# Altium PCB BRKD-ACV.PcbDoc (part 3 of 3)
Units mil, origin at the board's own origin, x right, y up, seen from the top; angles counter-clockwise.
Board outline 5708.66 x 3740.16 mil, 4 copper layers (L1-TOP, L2-GND, L3-PWR, L4-BOT), stack 61.722 mil thick; 171 components, 263 nets, 918 pads, 406 vias.
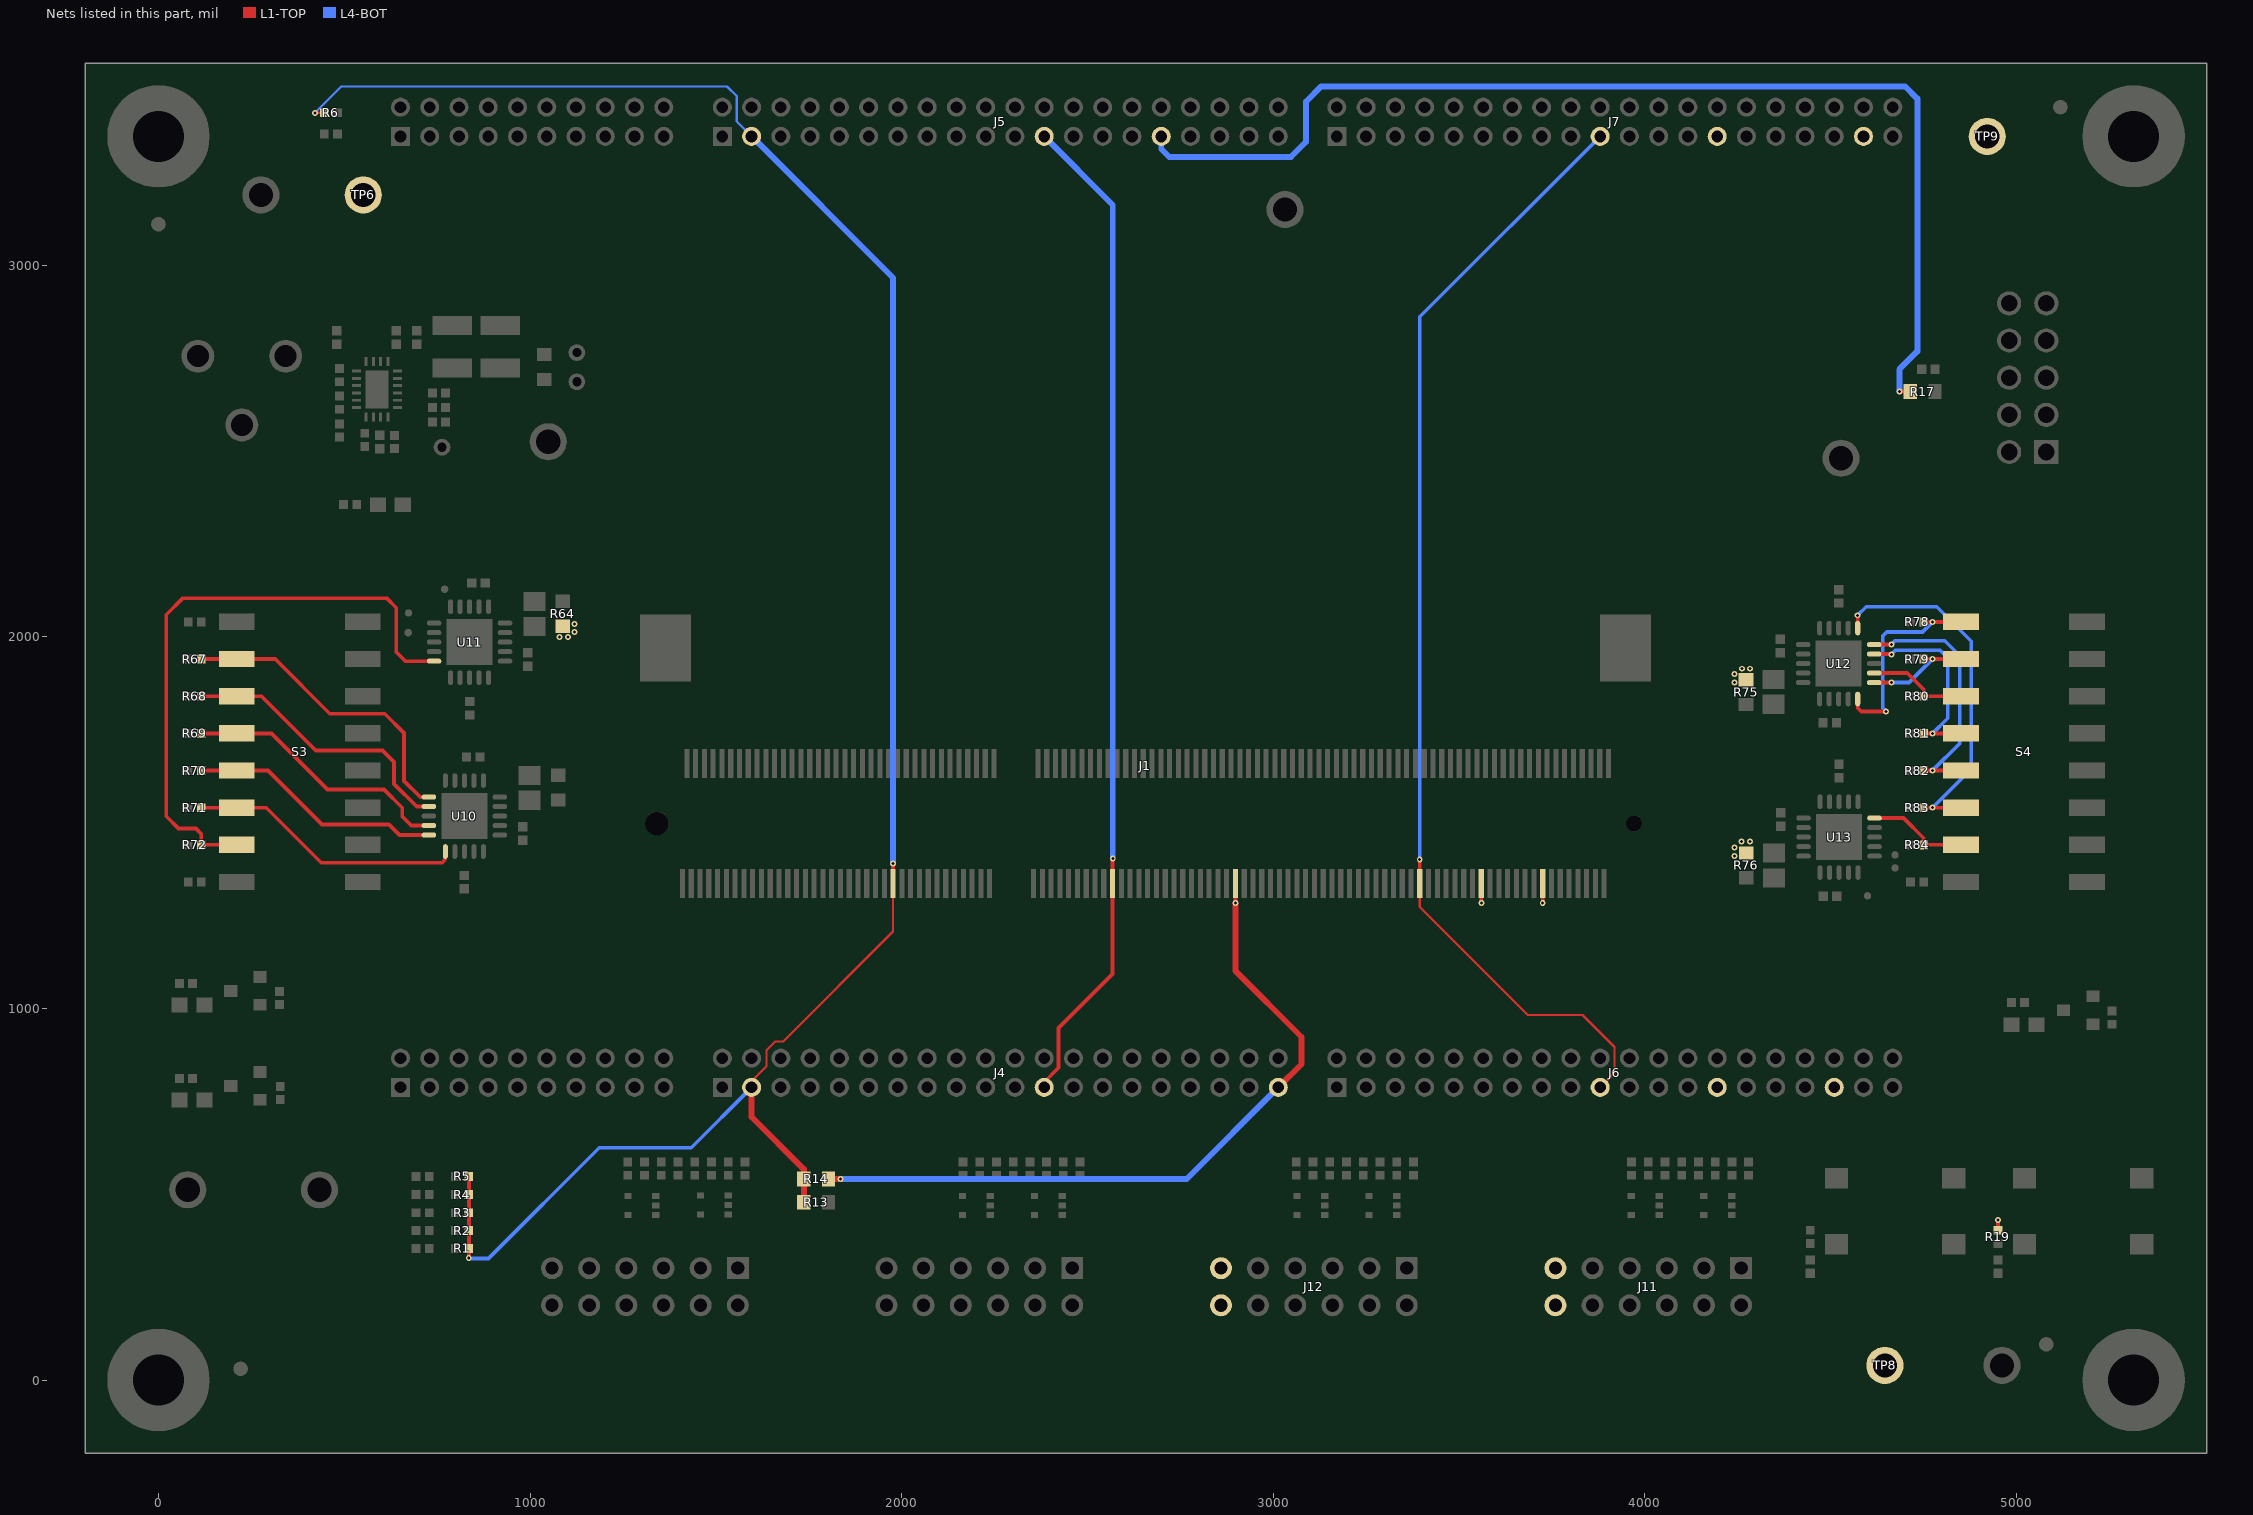
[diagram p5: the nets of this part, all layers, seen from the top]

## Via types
v1: diameter 16, hole 8, L1-TOP to L4-BOT, tented both sides, 406 vias

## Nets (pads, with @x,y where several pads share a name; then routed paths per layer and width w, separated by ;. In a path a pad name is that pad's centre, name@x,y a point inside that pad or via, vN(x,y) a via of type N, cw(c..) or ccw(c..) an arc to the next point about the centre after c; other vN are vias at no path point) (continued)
VCCIO1_100MV: R67.2 S3.2 U10.6 | length 841.6
  L1-TOP w10: R67.2@115.43,1940 S3.2@210.5,1940 314,1940 461,1793 609,1793 661,1741 661,1612 704.24,1568.76 U10.6@727.71,1568.76
VCCIO1_200MV: R68.2 S3.3 U10.7 | length 769.8
  L1-TOP w10: R68.2@115.43,1840 S3.3@210.5,1840 277,1840 423,1694 603,1694 634,1663 634,1604 694.83,1543.17 U10.7@727.71,1543.17
VCCIO1_400MV: R69.2 S3.4 U10.9 | length 729.1
  L1-TOP w10: R69.2@115.43,1740 S3.4@210.5,1740 304,1740 455,1589 607,1589 656,1540 656,1516 680.02,1491.98 U10.9@727.71,1491.98
VCCIO1_800MV: R70.2 S3.5 U10.10 | length 684.2
  L1-TOP w10: R70.2@115.43,1640 S3.5@210.5,1640 295,1640 440,1495 620,1495 648.61,1466.39 U10.10@727.71,1466.39
VCCIO1_1600MV: R71.2 S3.6 U10.11 | length 742.7
  L1-TOP w10: R71.2@115.43,1540 S3.6@210.5,1540 290,1540 438,1392 763,1392 772,1401 U10.11@772,1422.1
VCCIO2: J1.175 J6.27 J7.27 J11.6 J11.12 J12.6 J12.12 R19.2 R75.2 TP8.1 | length 79.4
  L1-TOP w10: J1.175@3559.56,1335.92 3559.56,1284.44 v1(3560,1284) ; R19.2@4950,402.72 v1(4950,430)
  other v1: 4241,1877 4241,1900 4261,1914 4283,1914
VCCIO2_50MV: R78.2 S4.1 U12.5 | length 561.3
  L1-TOP w10: U12.5@4572.54,1832.39 4572.54,1808.46 4582,1799 v1(4649,1799) ; R78.2@4750,2040 v1(4774,2040) S4.1@4850.5,2040
  L4-BOT w10: v1(4649,1799) 4640,1808 4640,2002 4651,2013 4747,2013 v1(4774,2040)
VCCIO2_100MV: R79.2 S4.2 U12.6 | length 284
  L1-TOP w10: U12.6@4616.83,1876.69 4662.68,1876.69 v1(4663,1877) ; R79.2@4750,1940 v1(4774,1940) S4.2@4850.5,1940
  L4-BOT w10: v1(4663,1877) 4710.73,1877 4710.87,1876.87 v1(4774,1940)
VCCIO2_200MV: R80.2 S4.3 U12.7 | length 270
  L1-TOP w10: U12.7@4616.83,1902.28 4705.72,1902.28 4750,1858 R80.2@4750,1840 S4.3@4850.5,1840
VCCIO2_400MV: R81.2 S4.4 U12.9 | length 532
  L1-TOP w10: U12.9@4616.83,1953.46 v1@4663,1953.46 ; R81.2@4750,1740 v1(4774,1740) S4.4@4850.5,1740
  L4-BOT w10: v1(4663,1952.87) 4674.13,1964 4794,1964 4815,1943 4815,1781 v1(4774,1740)
VCCIO2_800MV: R82.2 S4.5 U12.10 | length 690.7
  L1-TOP w10: U12.10@4616.83,1979.05 v1@4663,1979.05 ; R82.2@4750,1640 v1(4774,1640) S4.5@4850.5,1640
  L4-BOT w10: v1(4663,1978.87) 4673.13,1989 4807,1989 4847,1949 4847,1713 v1(4774,1640)
VCCIO2_1600MV: R83.2 S4.6 U12.11 | length 979.9
  L1-TOP w10: v1(4572.36,2057.87) 4572.54,2057.69 U12.11@4572.54,2023.34 ; R83.2@4750,1540 v1(4774,1540) S4.6@4850.5,1540
  L4-BOT w10: v1(4572.36,2057.87) 4595.5,2081 4785,2081 4878,1988 4878,1644 v1(4774,1540)
VCCPD1: J1.119 J4.39 J5.31 R14.1 R17.2 R64.2 TP6.1 | length 5030.9
  L1-TOP w10: v1(2898,1284) 2898.14,1284.14 J1.119@2898.14,1335.92 ; v1(4684.54,2660) R17.2@4714.07,2660
  L1-TOP w16: R14.1@1803.46,541 v1(1835,541) ; v1(2898,1284) 2898,1101 3076,923 3076,850.02 J4.39@3013.39,787.4
  L4-BOT w16: v1(1835,541) 2766.98,541 J4.39@3013.39,787.4 ; J5.31@2698.43,3346.46 2698.43,3312.57 2720,3291 3047,3291 3088,3332 3088,3440 3129,3481 4700,3481 4733,3448 4733,2768 4684.54,2719.54 v1(4684.54,2660)
  other v1: 1079,1999 1102,1999 1120,2013 1120,2034
VCCPD1_25B_33: R72.2 S3.7 U11.10 | length 1660
  L1-TOP w10: S3.7@210.5,1440 R72.2@115.43,1440 115.43,1469.57 101,1484 54,1484 21,1517 21,2059 66,2104 614,2104 640,2078 640,1959 664.61,1934.39 U11.10@741.71,1934.39
VCCPD2: J1.189 J6.35 J7.37 R76.2 TP9.1 | length 52
  L1-TOP w10: J1.189@3724.91,1335.92 3724.91,1284.09 v1(3725,1284)
  other v1: 4241,1410 4241,1433 4260,1449 4283,1449
VCCPD2_25B_33: R84.2 S4.7 U13.10 | length 273.1
  L1-TOP w10: U13.10@4617.83,1512.05 4695.95,1512.05 4750,1458 R84.2@4750,1440 S4.7@4850.5,1440
VCCPGM: J1.49 J4.3 J5.3 R1.2 R2.2 R3.1 R4.2 R5.1 R6.2 R13.2 R14.2 | length 5748.1
  L1-TOP w6: v1(421,3410) R6.2@446.28,3410 ; J4.3@1596.06,787.4 1596.06,804.06 1636,844 1636,887 1660,911 1681,911 1976.88,1206.88 J1.49@1976.88,1335.92
  L1-TOP w10: v1(835,328) 835.62,328.62 R5.1@835.62,549 ; J1.49@1976.88,1335.92 1976.88,1389.88 v1(1977,1390)
  L1-TOP w16: J4.3@1596.06,787.4 1596.06,707.94 1736.54,567.46 R14.2@1736.54,541 R13.2@1736.54,478
  L4-BOT w6: v1(421,3410) 492,3481 1530,3481 1556,3455 1556,3386.52 J5.3@1596.06,3346.46
  L4-BOT w10: v1@840,327 888,327 1186,625 1433.66,625 J4.3@1596.06,787.4
  L4-BOT w16: J5.3@1596.06,3346.46 1977,2965.52 v1(1977,1390)
VREF1: J1.91 J4.23 J5.23 | length 2711.9
  L1-TOP w10: J4.23@2383.46,787.4 2383.46,801.46 2422,840 2422,947 2567.43,1092.43 J1.91@2567.43,1335.92 2567.43,1402.43 v1(2568,1403)
  L4-BOT w16: J5.23@2383.46,3346.46 2568,3161.92 v1(2568,1403)
VREF2: J1.161 J6.19 J7.19 | length 3079.3
  L1-TOP w6: J1.161@3394.2,1335.92 3394.2,1272.8 3685,982 3832,982 3918,896 3918,825.87 J6.19@3879.53,787.4
  L1-TOP w10: v1(3394,1401) 3394.2,1400.8 J1.161@3394.2,1335.92
  L4-BOT w10: v1(3394,1401) 3394,2860.93 J7.19@3879.53,3346.46
pads on no net: FID1.FID? FID2.FID? FID3.FID? FID4.FID? J1.MH J1.MTG J8.6 J8.7 J8.8 J13.3

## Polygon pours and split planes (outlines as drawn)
VCCIO2 on L1-TOP "VCCIO2" (solid, pour order 1015): 4292,1866 4232,1866 4232,1924 4292,1924
VCCPD2 on L1-TOP "VCCPD2" (solid, pour order 1014): 4293,1400 4232,1400 4232,1458 4293,1458
VCCIO1 on L1-TOP "VCCIO1" (solid, pour order 1013): 1056,1579 1056,1521 1118,1521 1118,1579
VCCPD1 on L1-TOP "VCCPD1" (solid, pour order 1012): 1068,2047 1068,1990 1130,1990 1130,2047
+VDCIN on L1-TOP "VDC_JACK" (solid, pour order 1011): 286,2812.5 437.5,2812.5 450,2800 583,2800 583,2728 552,2728 545,2721 545,2671 511,2671 511,2704.99 505.99,2710 467,2710 455,2698 286,2698
DGND on L1-TOP "DGND" (solid, pour order 1009): 475,2550 475,2498 497,2476 525,2476 572,2429 679,2429 679,2487.92 648.42,2518.5 573.5,2518.5 567,2525 535,2525 535,2596.04 545.96,2607 545.96,2620.96 519.96,2620.96 506,2607 506,2550
+VDC on L4-BOT "VDC_IN" (solid, pour order 1010): 580,934 5327,934 5327,2123 5142,2123 5142,1844 4808,1510 4693,1510 4603,1600 4603,1866 4399,1866 4399,2026 4215,2026 3433,1244 1469,1244 1469,2237 990,2716 822,2716 822,2329 580,2329
DGND on L4-BOT "DGND" (solid, pour order 1008): 4603,1828 4603,2026 4416,2026 4324,1934 4324,1828
DGND on L4-BOT "DGND" (solid, pour order 1007): 4610,1540 4610,1312 4333,1312 4333,1474 4399,1540
DGND on L4-BOT "DGND" (solid, pour order 1006): 673.51,1609 673.51,1372.51 873.51,1372.51 1010.51,1509.51 1010.51,1609
DGND on L4-BOT "DGND" (solid, pour order 1005): 690,2084 690,1840 890,1840 1027,1977 1027,2084
DGND on L2-GND (split plane): 5491.71,3523.21 5491.72,-176.75 -176.75,-176.75 -176.75,3523.21
VCCIO2 on L3-PWR (split plane): 4422.44,1644.56 3638,1644.56 3636.04,1644.31 3634.22,1643.55 3632.65,1642.35 3631.45,1640.78 3630.69,1638.96 3630.44,1637 3630.44,1219 3630.69,1217.04 3631.14,1215.97 3631.45,1215.22 3632.65,1213.65 3923.65,922.65 3925.22,921.45 3927.04,920.69 3929,920.44 4465.44,920.44 4465.44,686 4465.69,684.04 4466.45,682.22 4467.65,680.65 4469.22,679.45 4471.04,678.69 4473,678.44 5011.44,678.44 5011.44,368.56 4803.15,368.56 4801.19,368.31 4799.37,367.55 4797.8,366.35 4796.6,364.78 4795.84,362.96 4795.58,361 4795.58,-97.44 4546.56,-97.44 4546.56,476 4546.31,477.96 4545.55,479.78 4544.35,481.35 4542.78,482.55 4540.96,483.31 4539,483.56 4370,483.56 4368.04,483.31 4366.22,482.55 4364.65,481.35 4363.45,479.78 4362.69,477.96 4362.44,476 4362.44,113.56 2822.56,113.56 2822.56,399.44 3125,399.44 3126.96,399.69 3128.78,400.45 3130.35,401.65 3131.55,403.22 3132.31,405.04 3132.56,407 3132.56,1182 3132.56,3379.44 4422.44,3379.44
VCCPD2 on L3-PWR (split plane): 4992.44,3275.28 4737,3275.28 4735.04,3275.02 4733.22,3274.27 4731.65,3273.07 4730.45,3271.5 4729.69,3269.67 4729.44,3267.72 4729.44,693.56 4480.56,693.56 4480.56,928 4480.31,929.96 4479.55,931.78 4478.35,933.35 4476.78,934.55 4474.96,935.31 4473,935.56 3932.13,935.56 3645.56,1222.13 3645.56,1629.44 4430,1629.44 4431.96,1629.69 4433.78,1630.45 4435.35,1631.65 4436.55,1633.22 4437.31,1635.04 4437.56,1637 4437.56,3379.44 4992.44,3379.44
VCCIO1 on L3-PWR (split plane): 3117.44,1182 3117.44,414.56 2815,414.56 2813.04,414.31 2811.22,413.55 2809.65,412.35 2808.45,410.78 2807.69,408.96 2807.44,407 2807.44,106 2807.69,104.04 2808.45,102.22 2809.65,100.65 2811.22,99.45 2813.04,98.69 2815,98.44 4370,98.44 4371.96,98.69 4373.78,99.45 4375.35,100.65 4376.55,102.22 4377.31,104.04 4377.56,106 4377.56,468.44 4531.44,468.44 4531.44,-97.44 737.56,-97.44 737.56,623 737.56,952.87 953.13,1168.44 1449,1168.44 1450.96,1168.69 1452.03,1169.14 1452.78,1169.45 1454.35,1170.65 1559.35,1275.65 1560.55,1277.22 1561.31,1279.04 1561.56,1281 1561.56,1745 1561.31,1746.96 1560.55,1748.78 1559.35,1750.35 1557.78,1751.55 1555.96,1752.31 1554,1752.56 1475,1752.56 1473.04,1752.31 1471.22,1751.55 1469.65,1750.35 1227.87,1508.56 1013.56,1508.56 1013.56,1576 1013.56,1953.44 1911.44,1953.44 1911.44,1325 1911.69,1323.04 1912.45,1321.22 1913.65,1319.65 1915.22,1318.45 1917.04,1317.69 1919,1317.44 2806.44,1317.44 2806.44,1245 2806.69,1243.04 2807.45,1241.22 2808.65,1239.65 2810.22,1238.45 2812.04,1237.69 2814,1237.44 2942,1237.44 2943.96,1237.69 2945.78,1238.45 2947.35,1239.65 2948.55,1241.22 2949.31,1243.04 2949.56,1245 2949.56,3379.44 3117.44,3379.44
VCCPD1 on L3-PWR (split plane): 2934.44,1252.56 2821.56,1252.56 2821.56,1325 2821.31,1326.96 2820.55,1328.78 2819.35,1330.35 2817.78,1331.55 2815.96,1332.31 2814,1332.56 1926.56,1332.56 1926.56,1961 1926.31,1962.96 1925.55,1964.78 1924.35,1966.35 1922.78,1967.55 1920.96,1968.31 1919,1968.56 1013.56,1968.56 1013.56,3031.5 1013.31,3033.45 1012.55,3035.28 1011.35,3036.85 1009.78,3038.05 1007.96,3038.8 1006,3039.06 480.01,3039.06 480.01,3260.15 1357.72,3260.15 1359.67,3260.41 1361.5,3261.17 1363.07,3262.37 1480.13,3379.44 2934.44,3379.44
+2.5VDD on L3-PWR (split plane): 1546.44,1284.13 1445.87,1183.56 950,1183.56 948.04,1183.31 946.97,1182.86 946.22,1182.55 944.65,1181.35 724.65,961.35 723.45,959.78 722.69,957.96 722.44,956 722.44,716.23 196.85,716.23 194.89,715.97 193.07,715.21 191.5,714.01 190.3,712.44 189.54,710.62 189.29,708.66 189.29,440.64 7.56,440.64 7.56,981.12 519.88,1493.44 1231,1493.44 1232.96,1493.69 1234.03,1494.14 1234.78,1494.45 1236.35,1495.65 1478.13,1737.44 1546.44,1737.44
DGND on L3-PWR (split plane): 5491.71,3523.21 5491.72,-176.75 -176.75,-176.75 -176.75,3523.21

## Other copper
L1-TOP:
  region net DGND: 460,2810 460,2885 974,2885 974,2810 653,2810 507,2810
  region net +VDC: 593,2728 623,2728 631,2720 631,2671 660,2671 686,2697 866,2697 866,2675 1059,2675 1059,2712 1011,2712 974,2749 763,2749 712,2800 658,2800 593,2800
  region net DGND: 1029.18,1533.57 993.18,1497.57 993.18,1475.57 967.18,1475.57 933.18,1509.57 898.18,1509.57 898.18,1524.57 942.18,1524.57 968.18,1550.57 968.18,1586.57 1029.18,1586.57
  region net NetC11_2: 967.8,1601.2 957.18,1590.57 957.18,1554.57 938.18,1535.57 898.18,1535.57 898.18,1583.57 889.18,1592.57 841.18,1592.57 841.18,1636.57 852.18,1647.57 852.18,1689.57 931.18,1689.57 967.18,1653.57 1097,1653.57 1097,1601.2
  region net +VDC: 993.18,1465.57 998.18,1470.57 1013.18,1470.57 1013.18,1419.57 987.18,1419.57 967.18,1439.57 939.18,1439.57 901.18,1401.57 867.18,1401.57 867.18,1442.57 888.18,1442.57 898.18,1452.57 898.18,1499.57 934.18,1499.57 968.18,1465.57
  region net +VDC: 1007.18,1933.57 1012.18,1938.57 1027.18,1938.57 1027.18,1887.57 1001.18,1887.57 981.18,1907.57 953.18,1907.57 915.18,1869.57 881.18,1869.57 881.18,1910.57 902.18,1910.57 912.18,1920.57 912.18,1967.57 948.18,1967.57 982.18,1933.57
  region net NetC13_2: 981.18,2068.57 971.18,2058.57 971.18,2022.57 952.18,2003.57 912.18,2003.57 912.18,2051.57 903.18,2060.57 855.18,2060.57 855.18,2104.57 866.18,2115.57 866.18,2157.57 945.18,2157.57 981.18,2121.57 1109,2121.57 1109,2068.57
  region net DGND: 1043.18,2001.57 1007.18,1965.57 1007.18,1943.57 981.18,1943.57 947.18,1977.57 912.18,1977.57 912.18,1992.57 956.18,1992.57 982.18,2018.57 982.18,2054.57 1043.18,2054.57
  region net +VDC: 4351.36,1979.87 4346.36,1974.87 4331.36,1974.87 4331.36,2025.87 4357.36,2025.87 4377.36,2005.87 4405.36,2005.87 4443.36,2043.87 4477.36,2043.87 4477.36,2002.87 4456.36,2002.87 4446.36,1992.87 4446.36,1945.87 4410.36,1945.87 4376.36,1979.87
  region net NetC19_2: 4377.36,1844.87 4387.36,1854.87 4387.36,1890.87 4406.36,1909.87 4446.36,1909.87 4446.36,1861.87 4455.36,1852.87 4503.36,1852.87 4503.36,1808.87 4492.36,1797.87 4492.36,1755.87 4413.36,1755.87 4377.36,1791.87 4252,1791.87 4252,1844.87
  region net DGND: 4315.36,1911.87 4351.36,1947.87 4351.36,1969.87 4377.36,1969.87 4411.36,1935.87 4446.36,1935.87 4446.36,1920.87 4402.36,1920.87 4376.36,1894.87 4376.36,1858.87 4315.36,1858.87
  region net +VDC: 4352.36,1512.87 4347.36,1507.87 4332.36,1507.87 4332.36,1558.87 4358.36,1558.87 4378.36,1538.87 4406.36,1538.87 4444.36,1576.87 4478.36,1576.87 4478.36,1535.87 4457.36,1535.87 4447.36,1525.87 4447.36,1478.87 4411.36,1478.87 4377.36,1512.87
  region net NetC21_2: 4378.36,1377.87 4388.36,1387.87 4388.36,1423.87 4407.36,1442.87 4447.36,1442.87 4447.36,1394.87 4456.36,1385.87 4504.36,1385.87 4504.36,1341.87 4493.36,1330.87 4493.36,1288.87 4414.36,1288.87 4378.36,1324.87 4253,1324.87 4253,1377.87
  region net DGND: 4316.36,1444.87 4352.36,1480.87 4352.36,1502.87 4378.36,1502.87 4412.36,1468.87 4447.36,1468.87 4447.36,1453.87 4403.36,1453.87 4377.36,1427.87 4377.36,1391.87 4316.36,1391.87
L4-BOT:
  region net DGND: 445,2885 445,2374 702,2374 702,2642 580,2764 556,2764 511,2809 511,2885
L2-GND (plane layer: these items are gaps in the copper):
  lines w12: 439,2846.05 439,2368 708,2368 708,2645 583,2770 559,2770 512,2817 512,2844
L3-PWR (plane layer: these items are gaps in the copper):
  lines w15: 439,2846 439,2368 708,2368 708,2645 583,2770 559,2770 519,2810 519,2845.8 ; 730,615.44 730,956 950,1176 1449,1176 1554,1281 1554,1745 1475,1745 1231,1501 1006,1501 ; 730,623 730,-105 1006,-105 4539,-105 ; 730,708.66 196.85,708.66 196.85,433.07 0,433.07 0,984.25 516.75,1501 1006,1501 ; 1006,1576 1006,1501 ; 2942,3387.31 2942,1245 2858,1245 2814,1245 2814,1325 1919,1325 1919,1961 1006,1961 ; 4746,686 4737,686 4737,3267.72 5000,3267.72 5000,3387 4737,3387 4430,3387 ; 1006,1501 1006,1961 ; 1006,1961 1006,3031.5 472.44,3031.5 472.44,3267.72 1357.72,3267.72 1477,3387 2578,3387 2942,3387 3125,3387 ; 3125,3387 3125,1182 3125,407 2815,407 2815,106 4370,106 4370,476 4539,476 4539,-105 ; 3125,3387 4430,3387 ; 4430,3387 4430,1637 3638,1637 3638,1219 3929,928 4473,928 4473,686 5019,686 5019,361 4803.15,361 4803.15,-105 4539,-105

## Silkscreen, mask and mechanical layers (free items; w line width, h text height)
Top Overlay:
  lines w8: -130,2100 92,2100 ; 5257,2097 5479,2097
  text "10:GND" at 4605,2883 h40
  text "9:TDI" at 5240,2881 h40
  text "5:TMS" at 5240,2674 h40
  text "3:TDO" at 5240,2579 h40
  text "4:VCC" at 4638.32,2575 h40
  text "2:GND" at 4638.32,2481 h40
  text "1:TCK" at 5240,2480 h40
  text "0.5V +" at -128,2117 h40
  text "0.5V +" at 5259,2114 h40
  text "0.05V" at -130.01,2020 h40
  text "0.05V" at 5260,2020 h40
  text "0.1V" at -130.01,1920 h40
  text "0.1V" at 5260,1920 h40
  text "0.2V" at -130.01,1820 h40
  text "0.2V" at 5260,1820 h40
  text "0.4V" at -130.01,1720 h40
  text "0.4V" at 5260,1720 h40
  text "0.8V" at -130.01,1620 h40
  text "0.8V" at 5260,1620 h40
  text "1.6V" at -120,1520 h40
  text "1.6V" at 5270,1520 h40
  text "PD2" at 5260,1425 h40
  text "PD1" at -70,1420 h40
  text "EN" at 5260,1325 h40
  text "EN" at -40,1320 h40
  text "PWR 1" at 270,1180 h50
  text "PWR 2" at 4900,1180 h50
  text "'.Assembly_Part_Num' / '.PCB_Revision'" at 403,37 h40
Outline:
  the board outline again, w3.94
Mechanical:
  lines w3.94: 1326.58,1526.87 ccw(c1356.11,1526.87) 1356.11,1497.34 2273.43,1497.34 ccw(c2273.43,1507.18) 2283.28,1507.18 2283.28,1635.13 cw(c2302.96,1635.13) 2322.65,1635.13 2322.65,1507.18 ccw(c2332.49,1507.18) 2332.49,1497.34 3958.47,1497.34 ccw(c3958.47,1526.87) 3988,1526.87 3988,2206 cw(c3988,2284.74) 3988,2363.48 3988,2885.13 ccw(c3958.47,2885.13) 3958.47,2914.66 1356.11,2914.66 ccw(c1356.11,2885.13) 1326.58,2885.13 1326.58,2363.48 cw(c1326.58,2284.74) 1326.58,2206 1326.58,1526.87
Fab Notes:
  drawing of 451 lines, arcs and shapes, not listed
  text "NOTES /  / 1. MATERIAL SELECTION: /      4-LAYER, 370HR, 0.062\" +/- 0.005 THICK /      SURFACE FINISH: ENIG (ELECTROLESS NICKEL, IMMERSION GOLD) /  / 2. SOLDER RESIST: GREEN LPI /  / 3. SILKSCREEN: WHITE / DO NOT REMOVE OVER TENTED VIAS. /  / 4. LOT CODE IDENTIFICATION: ADD TO SILKSCREEN /  / 5. DRILL SIZES ARE FINISHED SIZE AFTER PLATING. /  / 6. ELECTRICAL BARE BOARD TEST REQUIRED /  / 7. FABRICATE TO MEET EU ROHS DIRECTIVE /       / 8. PANELIZATION: /      1 PIECE PER ARRAY /      0.25-IN RAILS ON ALL SIDES /      0.25-IN TAB ROUTING WITH MOUSE-BITES FOR BOARD SEPARATION /      MOUSE BITE LOCATIONS INDICATED BY ::: /       / 9. BARREL RELIEF APPROVED FOR TENTED VIAS /  / 10. BOARD TO MEET OR EXCEED UL 94V-0 FLAMMABILITY RATING. /      SUPPLIER TO ADD 94V-0 MARKING IN SILKSCREEN. /       / 11. VIA FILL NOT REQUIRED" at -1927,4768 h60
  text ":::" at 3146,3624 h50 r180
  text ":::" at 1398,3600 h50
  text "Layer" at 6967.5,3587.5 h60
  text "Name" at 7377.41,3587.5 h60
  text "Material" at 8307.16,3587.5 h60
  text "Thickness" at 9166.92,3587.5 h60
  text "Constant" at 9816.76,3587.5 h60
  text "Board Layer Stack" at 10386.62,3587.5 h60
  text "1" at 6967.5,3467.5 h60
  text "Top Overlay" at 7377.41,3467.5 h60
  text "2" at 6967.5,3347.5 h60
  text "Top Solder" at 7377.41,3347.5 h60
  text "Solder Resist" at 8307.16,3347.5 h60
  text "0.40mil" at 9166.92,3347.5 h60
  text "3.5" at 9816.76,3347.5 h60
  text "3" at 6967.5,3227.5 h60
  text "L1-TOP" at 7377.41,3227.5 h60
  text "Copper" at 8307.16,3227.5 h60
  text "1.95mil" at 9166.92,3227.5 h60
  text "4" at 6967.5,3107.5 h60
  text "Dielectric1" at 7377.41,3107.5 h60
  text "2.27mil" at 9166.92,3107.5 h60
  text "4.2" at 9816.76,3107.5 h60
  text "5" at 6967.5,2987.5 h60
  text "Dielectric2" at 7377.41,2987.5 h60
  text "2.27mil" at 9166.92,2987.5 h60
  text "4.2" at 9816.76,2987.5 h60
  text "6" at 6967.5,2867.5 h60
  text "L2-GND" at 7377.41,2867.5 h60
  text "Copper" at 8307.16,2867.5 h60
  text "1.30mil" at 9166.92,2867.5 h60
  text "7" at 6967.5,2747.5 h60
  text "Dielectric3" at 7377.41,2747.5 h60
  text "14.00mil" at 9166.92,2747.5 h60
  text "4.2" at 9816.76,2747.5 h60
  text "8" at 6967.5,2627.5 h60
  text "Dielectric4" at 7377.41,2627.5 h60
  text "6.05mil" at 9166.92,2627.5 h60
  text "4.2" at 9816.76,2627.5 h60
  text "9" at 6967.5,2507.5 h60
  text "Dielectric5" at 7377.41,2507.5 h60
  text "6.05mil" at 9166.92,2507.5 h60
  text "4.2" at 9816.76,2507.5 h60
  text "10" at 6967.5,2387.5 h60
  text "Dielectric6" at 7377.41,2387.5 h60
  text "6.05mil" at 9166.92,2387.5 h60
  text "4.2" at 9816.76,2387.5 h60
  text "11" at 6967.5,2267.5 h60
  text "Dielectric7" at 7377.41,2267.5 h60
  text "14.00mil" at 9166.92,2267.5 h60
  text "4.2" at 9816.76,2267.5 h60
  text "12" at 6967.5,2147.5 h60
  text "L3-PWR" at 7377.41,2147.5 h60
  text "Copper" at 8307.16,2147.5 h60
  text "1.30mil" at 9166.92,2147.5 h60
  text "13" at 6967.5,2027.5 h60
  text "Dielectric8" at 7377.41,2027.5 h60
  text "2.27mil" at 9166.92,2027.5 h60
  text "4.2" at 9816.76,2027.5 h60
  text "14" at 6967.5,1907.5 h60
  text "Dielectric9" at 7377.41,1907.5 h60
  text "2.27mil" at 9166.92,1907.5 h60
  text "4.2" at 9816.76,1907.5 h60
  text "15" at 6967.5,1787.5 h60
  text "L4-BOT" at 7377.41,1787.5 h60
  text "Copper" at 8307.16,1787.5 h60
  text "1.95mil" at 9166.92,1787.5 h60
  text ":::" at 5553,1778 h50 r270
  text ":::" at -239,1721 h50 r90
  text "16" at 6967.5,1667.5 h60
  text "Bottom Solder" at 7377.41,1667.5 h60
  text "Solder Resist" at 8307.16,1667.5 h60
  text "0.40mil" at 9166.92,1667.5 h60
  text "3.5" at 9816.76,1667.5 h60
  text "17" at 6967.5,1547.5 h60
  text "Bottom Overlay" at 7377.41,1547.5 h60
  text ":::" at 896,-235 h50 r180
  text ":::" at 3652,-251 h50 r180
  text "All dimensions in millimeters unless otherwise specified." at 1410,-610 h50
Drill Drawing:
  circle w10: c6521.64,5205.83 r20
  circle w10: c6521.64,5205.83 r33.33
  lines w10: 6488.31,5089.17 6554.97,5089.17 6521.64,5022.5 6488.31,5089.17 ; 6488.31,5355.83 6521.64,5322.5 6554.97,5355.83 6521.64,5389.17 6488.31,5355.83 ; 6488.31,5472.5 6521.64,5489.17 6554.97,5472.5 6538.31,5505.83 6554.97,5539.17 6521.64,5522.5 6488.31,5539.17 6504.97,5505.83 6488.31,5472.5 ; 6488.31,5922.5 6554.97,5922.5 6554.97,5989.17 6488.31,5989.17 6488.31,5922.5 ; 6488.31,6072.5 6488.31,6089.17 6504.97,6105.83 6488.31,6122.5 6488.31,6139.17 6504.97,6139.17 6521.64,6122.5 6538.31,6139.17 6554.97,6139.17 6554.97,6122.5 6538.31,6105.83 6554.97,6089.17 6554.97,6072.5 6538.31,6072.5 6521.64,6089.17 6504.97,6072.5 6488.31,6072.5 ; 6488.31,6239.17 6504.97,6239.17 6504.97,6222.5 6538.31,6222.5 6538.31,6239.17 6554.97,6239.17 6554.97,6272.5 6538.31,6272.5 6538.31,6289.17 6504.97,6289.17 6504.97,6272.5 6488.31,6272.5 6488.31,6239.17 ; 6501.64,6085.83 6501.64,6095.83 6511.64,6105.83 6501.64,6115.83 6501.64,6125.83 6511.64,6125.83 6521.64,6115.83 6531.64,6125.83 6541.64,6125.83 6541.64,6115.83 6531.64,6105.83 6541.64,6095.83 6541.64,6085.83 6531.64,6085.83 6521.64,6095.83 6511.64,6085.83 6501.64,6085.83 ; 6501.64,6245.83 6511.64,6245.83 6511.64,6235.83 6531.64,6235.83 6531.64,6245.83 6541.64,6245.83 6541.64,6265.83 6531.64,6265.83 6531.64,6275.83 6511.64,6275.83 6511.64,6265.83 6501.64,6265.83 6501.64,6245.83
  lines w15: 6428.52,4827.5 12538.88,4827.5 ; 6428.52,6327.5 12538.88,6327.5 ; 6979.39,4677.5 6979.39,6477.5 ; 7579.23,4677.5 7579.23,6477.5 ; 8728.9,4677.5 8728.9,6477.5 ; 9234.77,4677.5 9234.77,6477.5 ; 9968.57,4677.5 9968.57,6477.5 ; 11158.23,4677.5 11158.23,6477.5 ; 11748.08,4677.5 11748.08,6477.5 ; 6428.52,4677.5 12538.88,4677.5 12538.88,6477.5 6428.52,6477.5 6428.52,4677.5
  text "Symbol" at 6518.52,6372.5 h72
  text "Count" at 7024.39,6372.5 h72
  text "Hole Size" at 7624.23,6372.5 h72
  text "Plated" at 8773.9,6372.5 h72
  text "Hole Type" at 9279.77,6372.5 h72
  text "Drill Layer Pair" at 10013.57,6372.5 h72
  text "Via/Pad" at 11203.23,6372.5 h72
  text "Pad Shape" at 11793.08,6372.5 h72
  text "1" at 7024.39,6222.5 h60
  text "43.31mil (1.100mm)" at 7624.23,6222.5 h60
  text "NPTH" at 8773.9,6222.5 h60
  text "Round" at 9279.77,6222.5 h60
  text "L1-TOP - L4-BOT" at 10013.57,6222.5 h60
  text "Pad" at 11203.23,6222.5 h60
  text "Rounded" at 11793.08,6222.5 h60
  text "1" at 7024.39,6072.5 h60
  text "62.99mil (1.600mm)" at 7624.23,6072.5 h60
  text "NPTH" at 8773.9,6072.5 h60
  text "Round" at 9279.77,6072.5 h60
  text "L1-TOP - L4-BOT" at 10013.57,6072.5 h60
  text "Pad" at 11203.23,6072.5 h60
  text "Rounded" at 11793.08,6072.5 h60
  text "3" at 7024.39,5922.5 h60
  text "25.00mil (0.635mm)" at 7624.23,5922.5 h60
  text "PTH" at 8773.9,5922.5 h60
  text "Round" at 9279.77,5922.5 h60
  text "L1-TOP - L4-BOT" at 10013.57,5922.5 h60
  text "Pad" at 11203.23,5922.5 h60
  text "Rounded" at 11793.08,5922.5 h60
  text "3" at 7024.39,5772.5 h60
  text "59.06mil (1.500mm)" at 7624.23,5772.5 h60
  text "PTH" at 8773.9,5772.5 h60
  text "Round" at 9279.77,5772.5 h60
  text "L1-TOP - L4-BOT" at 10013.57,5772.5 h60
  text "Pad" at 11203.23,5772.5 h60
  text "Rounded" at 11793.08,5772.5 h60
  text "B" at 6489.43,5762.51 h66.67
  text "4" at 7024.39,5622.5 h60
  text "137.80mil (3.500mm)" at 7624.23,5622.5 h60
  text "PTH" at 8773.9,5622.5 h60
  text "Round" at 9279.77,5622.5 h60
  text "L1-TOP - L4-BOT" at 10013.57,5622.5 h60
  text "Pad" at 11203.23,5622.5 h60
  text "Rounded" at 11793.08,5622.5 h60
  text "A" at 6489.43,5612.51 h66.67
  text "10" at 7024.39,5472.5 h60
  text "44.88mil (1.140mm)" at 7624.23,5472.5 h60
  text "PTH" at 8773.9,5472.5 h60
  text "Round" at 9279.77,5472.5 h60
  text "L1-TOP - L4-BOT" at 10013.57,5472.5 h60
  text "Pad" at 11203.23,5472.5 h60
  text "(Mixed)" at 11793.08,5472.5 h60
  text "10" at 7024.39,5322.5 h60
  text "65.00mil (1.651mm)" at 7624.23,5322.5 h60
  text "PTH" at 8773.9,5322.5 h60
  text "Round" at 9279.77,5322.5 h60
  text "L1-TOP - L4-BOT" at 10013.57,5322.5 h60
  text "Pad" at 11203.23,5322.5 h60
  text "Rounded" at 11793.08,5322.5 h60
  text "48" at 7024.39,5172.5 h60
  text "35.43mil (0.900mm)" at 7624.23,5172.5 h60
  text "PTH" at 8773.9,5172.5 h60
  text "Round" at 9279.77,5172.5 h60
  text "L1-TOP - L4-BOT" at 10013.57,5172.5 h60
  text "Pad" at 11203.23,5172.5 h60
  text "(Mixed)" at 11793.08,5172.5 h60
  text "200" at 7024.39,5022.5 h60
  text "31.50mil (0.800mm)" at 7624.23,5022.5 h60
  text "PTH" at 8773.9,5022.5 h60
  text "Round" at 9279.77,5022.5 h60
  text "L1-TOP - L4-BOT" at 10013.57,5022.5 h60
  text "Pad" at 11203.23,5022.5 h60
  text "(Mixed)" at 11793.08,5022.5 h60
  text "406" at 7024.39,4872.5 h60
  text "8.00mil (0.203mm)" at 7624.23,4872.5 h60
  text "PTH" at 8773.9,4872.5 h60
  text "Round" at 9279.77,4872.5 h60
  text "L1-TOP - L4-BOT" at 10013.57,4872.5 h60
  text "Via" at 11203.23,4872.5 h60
  text "Rounded" at 11793.08,4872.5 h60
  text "C" at 6489.43,4862.51 h66.67
  text "686 Total" at 7024.39,4722.5 h60
Doc-Assy-Top:
  lines w3.21: -749.62,141.31 -621.05,141.31 ; -749.62,1507.35 -621.05,1507.35 ; -749.62,2873.39 -621.05,2873.39 ; 889.63,-1096.16 889.63,-967.6 ; 889.63,3982.3 889.63,4110.86 ; 2657.45,-1096.16 2657.45,-967.6 ; 2657.45,3982.3 2657.45,4110.86 ; 3171.72,-1096.16 6064.52,-1096.16 ; 4009.44,-967.7 4009.44,-509.29 5935.95,-509.29 ; 4009.44,-813 5935.95,-813 ; 4300.17,-967.7 4300.17,-813 ; 4425.27,-1096.16 4425.27,-967.6 ; 4425.27,3982.3 4425.27,4110.86 ; 4751.22,-967.7 4751.22,-813 ; 4841.41,-812.81 4841.41,-509.29 ; 5418,-967.7 5418,-813 ; 5935.95,141.31 6064.52,141.31 ; 5935.95,1507.35 6064.52,1507.35 ; 5935.95,2873.39 6064.52,2873.39 ; 6064.52,-1096.16 6064.52,4110.86 -749.62,4110.86 -749.62,-1096.16 6064.52,-1096.16 ; -621.05,-967.6 -621.05,3982.3 5935.95,3982.3 5935.95,-967.6 -621.05,-967.6
  text "1" at -9.49,4026.11 h45
  text "2" at 1758.75,4026.11 h45
  text "3" at 3523.36,4026.11 h45
  text "4" at 5291.82,4026.11 h45
  text "A" at -703.43,3498.24 h45
  text "A" at 5986.19,3498.24 h45
  text "B" at -703.43,2132.19 h45
  text "B" at 5986.19,2132.19 h45
  text "C" at -703.43,766.15 h45
  text "C" at 5986.19,766.15 h45
  text "TITLE:" at 4059.37,-559.91 h28.93
  text "Opal Kelly" at 4892.03,-580.16 h45
  text "D" at -703.43,-596.68 h45
  text "D" at 5986.19,-596.68 h45
  text "13500 SW 72nd Ave Suite 100" at 4892.03,-656.09 h45
  text "Portland, OR 97223" at 4892.03,-719.36 h45
  text "'.Assembly_Part_Num' / Assembly Drawing" at 4080.18,-720.44 h45
  text "www.opalkelly.com" at 4892.03,-782.63 h45
  text "(Top)" at 4080.18,-793.72 h45
  text "REV:" at 4045.23,-855.86 h28.93
  text "SIZE:" at 4339.39,-855.86 h28.93
  text "ENGINEER:" at 4790.45,-855.86 h28.93
  text "DATE:" at 5457.22,-855.86 h28.93
  text ".Assembly_Revision" at 4084.45,-934.31 h45
  text "ANSI A" at 4378.61,-934.31 h45
  text "NDK" at 4829.67,-934.31 h45
  text ".PRINT_DATE" at 5496.44,-934.31 h45
  text "1" at -9.49,-1056.4 h45
  text "2" at 1758.75,-1056.4 h45
  text "3" at 3523.36,-1056.4 h45
  text "4" at 5291.82,-1056.4 h45
Doc-Assy-Bot:
  lines w4.8: -2464.68,305.96 -2272.59,305.96 ; -2464.68,2346.88 -2272.59,2346.88 ; -2464.68,4387.81 -2272.59,4387.81 ; -2272.01,-1119.27 1256.86,-1119.27 ; -2270.97,-888.15 1256.86,-888.15 1256.86,-434.4 -2269.93,-434.4 ; -727.25,-1119.27 -727.25,-888.15 ; -15.57,-1542.88 -15.57,-1350.79 ; -15.57,6044.55 -15.57,6236.64 ; 13.87,-887.86 13.87,-434.4 ; 1256.86,-1347.66 1256.86,-774.43 ; 1857.28,-1542.88 -2464.68,-1542.88 ; 2625.63,-1542.88 2625.63,-1350.79 ; 2625.63,6044.55 2625.63,6236.64 ; 5266.82,-1542.88 5266.82,-1350.79 ; 5266.82,6044.55 5266.82,6236.64 ; 7523.84,305.96 7715.93,305.96 ; 7523.84,2346.88 7715.93,2346.88 ; 7523.84,4387.81 7715.93,4387.81 ; -2464.68,-1542.88 -2464.68,6236.64 7715.93,6236.64 7715.93,-1542.88 -2464.68,-1542.88 ; -2272.59,-1350.79 -2272.59,6044.55 7523.84,6044.55 7523.84,-1350.79 -2272.59,-1350.79
  text "4" at -1310.24,6110.01 h67.23
  text "3" at 1331.92,6110.01 h67.23
  text "2" at 3968.31,6110.01 h67.23
  text "1" at 6610.15,6110.01 h67.23
  text "A" at -2347.65,5321.35 h67.23
  text "A" at 7646.92,5321.35 h67.23
  text "B" at -2347.65,3280.42 h67.23
  text "B" at 7646.92,3280.42 h67.23
  text "C" at -2347.65,1239.5 h67.23
  text "C" at 7646.92,1239.5 h67.23
  text "TITLE:" at 1182.28,-510.03 h43.22
  text "Opal Kelly" at -61.75,-540.28 h67.23
  text "13500 SW 72nd Ave Suite 100" at -61.75,-653.71 h67.23
  text "Portland, OR 97223" at -61.75,-748.24 h67.23
  text "BRK-FOMD-ACV-A4 / Assembly Drawing" at 1151.19,-749.86 h67.23
  text "D" at -2347.65,-796.62 h67.23
  text "D" at 7646.92,-796.62 h67.23
  text "www.opalkelly.com" at -61.75,-842.78 h67.23
  text "(Bottom)" at 1151.19,-859.35 h67.23
  text "DATE:" at 1182.28,-963.77 h43.22
  text "SIZE:" at -818,-965 h43.22
  text "TIME:" at 399.66,-965 h43.22
  text "ANSI A" at -863.38,-1080.25 h67.23
  text ".Print_Time" at 351.64,-1080.25 h67.23
  text ".PRINT_DATE" at 1145.7,-1080.25 h67.23
  text "FILE NAME:" at 1182.28,-1190.65 h43.22
  text ".PCB_FILE_NAME" at 1144.46,-1304.09 h67.23
  text "4" at -1310.24,-1483.48 h67.23
  text "3" at 1331.92,-1483.48 h67.23
  text "2" at 3968.31,-1483.48 h67.23
  text "1" at 6610.15,-1483.48 h67.23
Doc-Fab:
  lines w5: 9011,-1792.14 9011,-736 13550.19,-736 ; 9011,-1256 10771,-1256 ; 9011,-1146 10771,-1146 ; 9011,-926 10771,-926 ; 9011,-816 10771,-816 ; 9431,-1792.14 9431,-736 ; 10771,-1792.14 10771,-736 ; 10771,-1596 13551,-1596 ; 10771,-1156 13550.19,-1156 ; 11331,-1792.14 11331,-1596 ; 12011,-1596 12011,-1156 ; 12661,-1792.14 12661,-1596
  lines w5.49: -2711.49,597.47 -2491.7,597.47 ; -2711.49,3207.41 -2491.7,3207.41 ; -2711.49,5817.35 -2491.7,5817.35 ; 35.82,-2012.47 35.82,-1792.68 ; 35.82,8207.51 35.82,8427.29 ; 2783.12,-2012.47 2783.12,-1792.68 ; 2783.12,8207.51 2783.12,8427.29 ; 5530.43,-2012.47 5530.43,-1792.68 ; 5530.43,8207.51 5530.43,8427.29 ; 8277.73,-2012.47 8277.73,-1792.68 ; 8277.73,8207.51 8277.73,8427.29 ; 11025.04,-2012.47 11025.04,-1792.68 ; 11025.04,8207.51 11025.04,8427.29 ; 13552.56,597.47 13772.34,597.47 ; 13552.56,3207.41 13772.34,3207.41 ; 13552.56,5817.35 13772.34,5817.35 ; -2711.49,-2012.47 13772.34,-2012.47 13772.34,8427.29 -2711.49,8427.29 -2711.49,-2012.47 ; -2491.7,-1792.68 13552.56,-1792.68 13552.56,8207.51 -2491.7,8207.51 -2491.7,-1792.68
  text "1" at -1358.35,8284.43 h76.92
  text "2" at 1384.19,8284.43 h76.92
  text "3" at 4119.79,8284.43 h76.92
  text "4" at 6874.42,8284.43 h76.92
  text "5" at 9620.61,8284.43 h76.92
  text "6" at 12373.41,8284.43 h76.92
  text "A" at -2629.07,7028.36 h76.92
  text "A" at 13634.98,7028.36 h76.92
  text "B" at -2629.07,4412.93 h76.92
  text "B" at 13634.98,4412.93 h76.92
  text "C" at -2629.07,1802.99 h76.92
  text "C" at 13634.98,1802.99 h76.92
  text "REVISION:" at 9040,-796 h40
  text "DESCRIPTION:" at 9470,-796 h40
  text "D" at -2629.07,-801.46 h76.92
  text "D" at 13634.98,-801.46 h76.92
  text "PART NUMBER:" at 10851,-876 h75
  text "20160615" at 9041,-896 h50
  text "Initial Release" at 9471,-896 h50
  text "20160916" at 9041,-1006 h50
  text "Fixed LDO config pins, FPGA config pin ties, added OVP bypass" at 9465,-1141.14 h50
  text "'.PCB_Part_Num'-'.PCB_Revision'" at 10871,-1156 h130
  text "20170316" at 9041,-1226 h50
  text "Fixed silk label typos" at 9471,-1226 h50
  text "TITLE:" at 10831,-1236 h40
  text "Opal Kelly" at 12071,-1256 h60
  text "13500 SW 72nd Ave Suite 100" at 12071,-1356 h60
  text "Portland, OR 97223" at 12071,-1456 h60
  text "'.Assembly_Part_Num' / Fabrication Drawing" at 10871,-1536 h60
  text "www.opalkelly.com" at 12071,-1556 h60
  text "SIZE:" at 10831,-1656 h40
  text "ENGINEER:" at 11391,-1656 h40
  text "DATE:" at 12711,-1656 h40
  text "ANSI A" at 10871,-1756 h60
  text "NDK" at 11431,-1756 h60
  text ".PRINT_DATE" at 12751,-1756 h60
  text "1" at -1358.35,-1935.54 h76.92
  text "2" at 1384.19,-1935.54 h76.92
  text "3" at 4119.79,-1935.54 h76.92
  text "4" at 6874.42,-1935.54 h76.92
  text "5" at 9620.61,-1935.54 h76.92
  text "6" at 12373.41,-1935.54 h76.92

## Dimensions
0,0 to 0,3346.46 on Dimensions
-196.85,-196.85 to -196.85,3543.31 on Dimensions
0,0 to -196.85,-196.85 on Dimensions
-196.85,3543.31 to 5511.81,3543.31 on Dimensions
0,3346.46 to 5314.96,3346.46 on Dimensions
